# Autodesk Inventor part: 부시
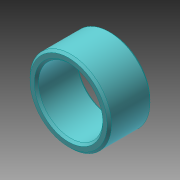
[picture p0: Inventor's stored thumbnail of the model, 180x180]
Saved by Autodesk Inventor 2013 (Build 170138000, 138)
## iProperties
Created: 2013-01
Part Number: 부시
Document SubType Name: Modeling
Designer: mdu
Density: 1 g/cm^3
Material: 강철, 연강
Author: mdu
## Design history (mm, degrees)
sketch "스케치1"
  geometry: L1 (15, 20)-(15, -46) reference; L2 (-20, 19)-(20, 19); L3 (30.7, -1)-(-30.7, -1) reference; L4 (19, 19)-(19, -1); L5 (15, -1)-(19, -1); L6 (0, 0)-(0, 19); L7 (19, 19)-(15, 19)
  constraints: 12 end point, 6 point on line, 1 collinear, 1 midpoint, 1 perpendicular, 1 vertical, 2 other
  dimensions: "d0" = 38 diameter of L4 L6; "d5" = 20 distance between parallel lines of L2 L3
revolve "회전1" sketch "스케치1" stored, may be unused: angle "d1" = 90 deg
chamfer "모따기1" distance "d2" = 1; stored, may be unused: second distance "d3" = 2, angle "d4" = 45 deg
node "솔리드1"
node "참조2"
